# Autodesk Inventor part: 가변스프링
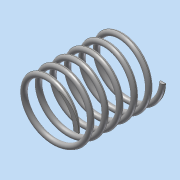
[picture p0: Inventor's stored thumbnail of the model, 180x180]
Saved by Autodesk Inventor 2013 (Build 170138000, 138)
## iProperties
Created: 2018-06
Part Number: 가변스프링
Material: 강철, 연강
Document SubType Name: Modeling
Designer: Administrator
Mass: 83.1659 g
Surface Area: 106.47 cm^2
Volume: 10.5809 cm^3
Density: 7.86 g/cm^3
Author: Administrator
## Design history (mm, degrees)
sketch "스케치1"
  geometry: L1 (0, 0)-(0, 66.014); L2 (0, 0)-(22.5, 0); L3 (0, 66.014)-(22.5, 66.014); C1 r 2 at (22.5, 0)
  constraints: 6 end point, 1 centre point, 1 coincident, 1 parallel, 1 perpendicular, 1 vertical
  dimensions: "d0" = 66.01393 distance of L1.start L1.end (derived); "d1" = 45 diameter of L3.end L1; "d2" = 45 diameter of L2.end L1; "d3" = 4 diameter of C1
feature "코일1" sketch "스케치1" pitch "d4" = 10; turns "d6" = 6; dims "d5" = 66.01393 (= d0), "d7" = 0, angle "d8" = 90 deg, angle "d9" = 90 deg, "d10" = 0, "d11" = 0
sketch "스케치2"
  geometry: L1 (-25, 66.014)-(25, 66.014); L2 (25, 66.014)-(25, 0); L3 (25, 0)-(-25, 0); L4 (-25, 0)-(-25, 66.014); 2 further points
  constraints: 8 end point, 2 parallel, 1 coincident, 1 horizontal, 1 midpoint, 1 perpendicular
  dimensions: "d12" = 66.01393 distance of L1.end L2.end (derived); "d13" = 50 distance of L1.start L1.end
extrude "돌출1" sketch "스케치2" stored distance "d14" = 50; taper "d15" = 0 deg
node "솔리드1"
